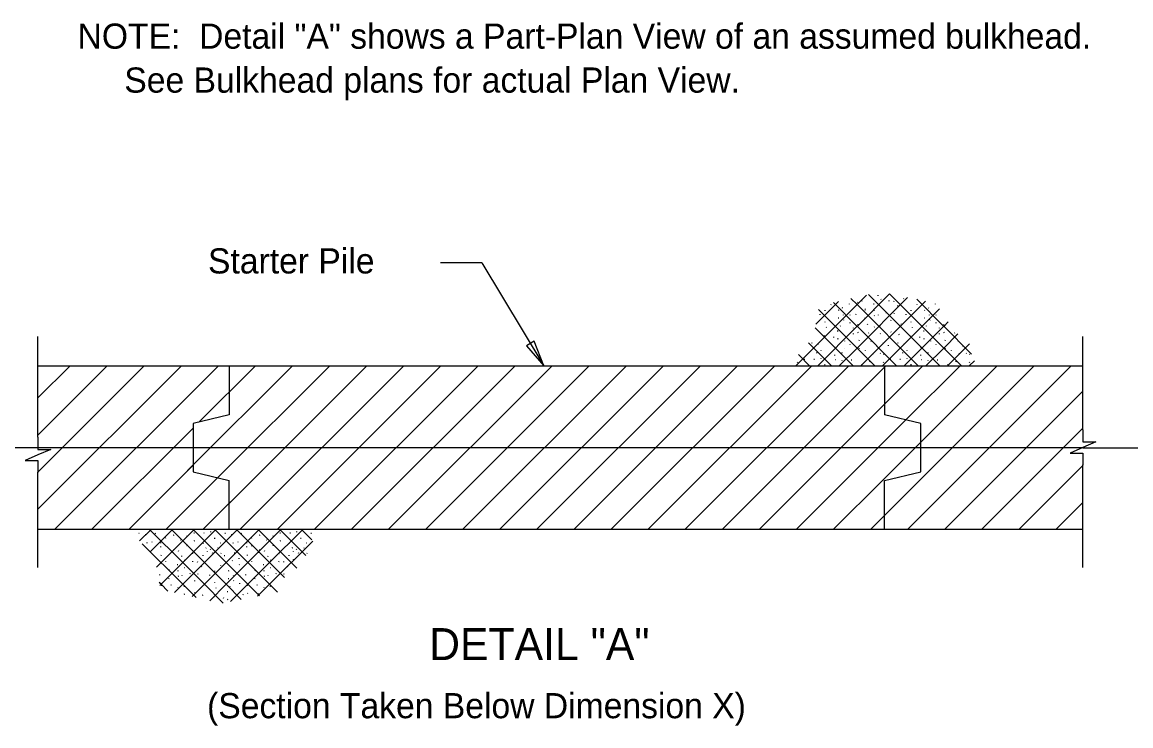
# Model space of a CAD drawing. Extents: x 0.4 to 30.4, y 0.1 to 19.4.
# Drawn here: x 4.37 to 11.03, y 0.94 to 5.17 of the extents above; entities that cross this region are included whole.
import ezdxf

# ---------------------------------------------------------------- set-up
doc = ezdxf.new("R2010")
doc.units = 0
for name, color, linetype in [('Dimension', 7, 'Continuous'), ('Miscellaneous', 7, 'Continuous'), ('SheetPileConc', 7, 'Continuous'), ('TextStructures', 7, 'Continuous')]:
    doc.layers.add(name, color=color, linetype=linetype)

msp = doc.modelspace()

# ---------------------------------------------------------------- linework, layer by layer
at = {"layer": 'Dimension'}
for p, q in [((7.1326, 3.7252), (6.8827, 3.7252)), ((7.1326, 3.7252), (7.5037, 3.1066)), ((4.4653, 2.6773), (4.4653, 3.2816)), ((10.7426, 2.7215), (10.7426, 3.2816)), ((4.4653, 1.8953), (4.4653, 2.4666)), ((10.7426, 1.8953), (10.7426, 2.5109))]:
    msp.add_line(p, q, dxfattribs=at)
msp.add_lwpolyline([(7.5037, 3.1066), (7.4461, 3.2542), (7.4007, 3.2269)], close=True, dxfattribs=at)
for points in [[(4.4653, 2.677), (4.4653, 2.6045), (4.5428, 2.6045), (4.4653, 2.5708), (4.3878, 2.537), (4.4653, 2.537), (4.4653, 2.4645)], [(10.7426, 2.7213), (10.7426, 2.6488), (10.8201, 2.6488), (10.7426, 2.615), (10.6651, 2.5813), (10.7426, 2.5813), (10.7426, 2.5088)]]:
    msp.add_lwpolyline(points, dxfattribs=at)
at = {"layer": 'Miscellaneous'}
for p, q in [((9.3854, 3.3431), (9.5807, 3.5385)), ((9.3854, 3.4734), (9.4431, 3.5311)), ((9.8835, 3.1055), (9.4551, 3.5338)), ((9.5121, 3.5267), (9.5129, 3.5298)), ((9.9062, 3.2129), (9.5806, 3.5385)), ((9.0191, 3.1071), (9.3854, 3.4734)), ((9.1373, 3.3555), (9.2742, 3.4924)), ((9.229, 3.4714), (9.2297, 3.4743)), ((9.3854, 3.3431), (9.2432, 3.4853)), ((9.34, 3.4756), (9.3407, 3.4786)), ((9.3854, 3.4734), (9.3492, 3.5096)), ((9.3854, 3.2129), (9.6891, 3.5167)), ((9.753, 3.1057), (9.3854, 3.4734)), ((9.3888, 3.4853), (9.3904, 3.4891)), ((9.409, 3.1063), (9.7974, 3.4948)), ((9.4159, 3.4937), (9.4166, 3.4966)), ((9.4881, 3.4763), (9.4842, 3.4756)), ((9.5302, 3.5049), (9.5279, 3.5057)), ((9.5775, 3.4944), (9.579, 3.4974)), ((9.607, 3.4927), (9.6078, 3.4958)), ((9.6308, 3.4645), (9.6315, 3.4674)), ((9.6658, 3.5079), (9.6651, 3.5094)), ((9.9062, 3.3431), (9.7438, 3.5056)), ((9.7459, 3.4714), (9.7466, 3.4743)), ((9.8569, 3.4756), (9.8576, 3.4786)), ((9.3854, 3.2129), (9.1535, 3.4448)), ((9.1632, 3.4124), (9.1639, 3.4154)), ((9.1933, 3.4365), (9.194, 3.4395)), ((9.2768, 3.4395), (9.273, 3.4387)), ((9.2993, 3.4523), (9.2971, 3.4546)), ((9.3038, 3.4102), (9.3046, 3.4132)), ((9.3437, 3.4102), (9.3444, 3.4132)), ((9.379, 3.4151), (9.3797, 3.418)), ((9.4346, 3.4402), (9.4362, 3.4433)), ((9.4362, 3.4455), (9.4369, 3.4486)), ((9.4911, 3.4079), (9.4881, 3.4072)), ((9.4891, 3.4385), (9.4899, 3.4415)), ((9.5136, 3.4094), (9.5143, 3.4124)), ((9.5302, 3.4575), (9.5279, 3.4583)), ((9.539, 3.1061), (9.8813, 3.4485)), ((9.5625, 3.423), (9.5633, 3.426)), ((9.6087, 3.4208), (9.6102, 3.4238)), ((9.6801, 3.4124), (9.6808, 3.4154)), ((9.7102, 3.4365), (9.7109, 3.4395)), ((9.7936, 3.4395), (9.7899, 3.4387)), ((9.8162, 3.4523), (9.814, 3.4546)), ((9.8207, 3.4102), (9.8214, 3.4132)), ((9.8606, 3.4102), (9.8613, 3.4132)), ((9.3617, 3.1064), (9.1335, 3.3346)), ((9.1491, 3.1068), (9.3854, 3.3432)), ((9.1933, 3.3673), (9.194, 3.3703)), ((9.2008, 3.3353), (9.2016, 3.3383)), ((9.2768, 3.3922), (9.273, 3.3914)), ((9.285, 3.3433), (9.2858, 3.3462)), ((9.3063, 3.3799), (9.3071, 3.3829)), ((9.3437, 3.3628), (9.3444, 3.3658)), ((9.3639, 3.332), (9.3647, 3.335)), ((9.6226, 3.1059), (9.3854, 3.3432)), ((9.3918, 3.3531), (9.3888, 3.3523)), ((9.4346, 3.3929), (9.4362, 3.3959)), ((9.4497, 3.3531), (9.4475, 3.3553)), ((9.4888, 3.3372), (9.4904, 3.3402)), ((9.5271, 3.347), (9.5242, 3.3455)), ((9.5893, 3.3786), (9.5907, 3.3816)), ((9.65, 3.3553), (9.6485, 3.3575)), ((9.6689, 3.1059), (9.9062, 3.3432)), ((9.7102, 3.3673), (9.7109, 3.3703)), ((9.7177, 3.3353), (9.7185, 3.3383)), ((9.7936, 3.3922), (9.7899, 3.3914)), ((9.8019, 3.3433), (9.8027, 3.3462)), ((9.8232, 3.3799), (9.824, 3.3829)), ((9.8606, 3.3628), (9.8613, 3.3658)), ((9.8808, 3.332), (9.8816, 3.335)), ((9.9087, 3.3531), (9.9057, 3.3523)), ((9.9062, 3.3431), (9.9328, 3.3697)), ((10.0725, 3.1768), (9.9062, 3.3432)), ((9.1903, 3.2846), (9.191, 3.2876)), ((9.246, 3.2763), (9.2467, 3.2794)), ((9.2715, 3.3146), (9.267, 3.3139)), ((9.2715, 3.2673), (9.267, 3.2665)), ((9.3639, 3.2966), (9.3647, 3.2996)), ((9.3918, 3.3057), (9.3888, 3.3049)), ((9.4549, 3.3012), (9.4557, 3.3042)), ((9.5271, 3.2996), (9.5242, 3.2982)), ((9.5908, 3.3079), (9.5894, 3.3102)), ((9.638, 3.2937), (9.6342, 3.2929)), ((9.7072, 3.2846), (9.7079, 3.2876)), ((9.7629, 3.2763), (9.7636, 3.2794)), ((9.7884, 3.3146), (9.7839, 3.3139)), ((9.7884, 3.2673), (9.7839, 3.2665)), ((9.8808, 3.2966), (9.8816, 3.2996)), ((9.9087, 3.3057), (9.9057, 3.3049)), ((9.9062, 3.2129), (9.9916, 3.2983)), ((9.9718, 3.3012), (9.9726, 3.3042)), ((9.2312, 3.1067), (9.0943, 3.2436)), ((9.1143, 3.2427), (9.115, 3.2457)), ((9.1505, 3.235), (9.1512, 3.238)), ((9.1693, 3.1974), (9.17, 3.2004)), ((9.2512, 3.2161), (9.2527, 3.2192)), ((9.279, 3.1066), (9.3854, 3.2129)), ((9.3128, 3.2545), (9.3121, 3.256)), ((9.3128, 3.2072), (9.3121, 3.2087)), ((9.3437, 3.2312), (9.3444, 3.2342)), ((9.4921, 3.1062), (9.3854, 3.2129)), ((9.3986, 3.2583), (9.3993, 3.262)), ((9.3986, 3.2109), (9.3993, 3.2146)), ((9.4362, 3.1958), (9.4369, 3.1989)), ((9.4708, 3.2516), (9.4693, 3.2523)), ((9.5053, 3.2244), (9.5023, 3.223)), ((9.5369, 3.2432), (9.5362, 3.2447)), ((9.5738, 3.2267), (9.5745, 3.2297)), ((9.6311, 3.2427), (9.6319, 3.2457)), ((9.6673, 3.235), (9.6681, 3.238)), ((9.6862, 3.1974), (9.6869, 3.2004)), ((9.7681, 3.2161), (9.7696, 3.2192)), ((9.7989, 3.1056), (9.9062, 3.2129)), ((9.8297, 3.2545), (9.829, 3.256)), ((9.8297, 3.2072), (9.829, 3.2087)), ((9.8606, 3.2312), (9.8613, 3.2342)), ((10.0139, 3.1052), (9.9062, 3.2129)), ((9.9155, 3.2583), (9.9162, 3.262)), ((9.9155, 3.2109), (9.9162, 3.2146)), ((9.9289, 3.1054), (10.061, 3.2375)), ((9.9531, 3.1958), (9.9538, 3.1989)), ((9.9877, 3.2516), (9.9862, 3.2523)), ((10.0222, 3.2244), (10.0192, 3.223)), ((9.1008, 3.1069), (9.0329, 3.1748)), ((9.071, 3.144), (9.0672, 3.1432)), ((9.1301, 3.144), (9.1264, 3.1432)), ((9.1436, 3.1824), (9.1444, 3.1853)), ((9.1693, 3.1492), (9.17, 3.1523)), ((9.2512, 3.1688), (9.2527, 3.1718)), ((9.2564, 3.1417), (9.2534, 3.141)), ((9.2956, 3.1824), (9.2956, 3.1853)), ((9.2956, 3.135), (9.2956, 3.138)), ((9.3542, 3.1402), (9.3505, 3.1395)), ((9.4625, 3.1305), (9.464, 3.1335)), ((9.464, 3.129), (9.4647, 3.132)), ((9.4835, 3.1786), (9.4798, 3.1779)), ((9.5256, 3.1801), (9.5242, 3.1824)), ((9.5444, 3.1733), (9.546, 3.1763)), ((9.5879, 3.144), (9.5841, 3.1432)), ((9.647, 3.144), (9.6433, 3.1432)), ((9.6605, 3.1824), (9.6613, 3.1853)), ((9.6862, 3.1492), (9.6869, 3.1523)), ((9.7681, 3.1688), (9.7696, 3.1718)), ((9.7733, 3.1417), (9.7703, 3.141)), ((9.8125, 3.1824), (9.8125, 3.1853)), ((9.8125, 3.135), (9.8125, 3.138)), ((9.8711, 3.1402), (9.8673, 3.1395)), ((9.9794, 3.1305), (9.9809, 3.1335)), ((9.9809, 3.129), (9.9816, 3.132)), ((10.0004, 3.1786), (9.9967, 3.1779)), ((10.0425, 3.1801), (10.041, 3.1824)), ((10.0588, 3.1051), (10.0902, 3.1365)), ((10.0613, 3.1733), (10.0629, 3.1763)), ((4.4653, 2.9132), (4.6587, 3.1066)), ((4.4653, 2.6905), (4.8814, 3.1066)), ((4.4653, 2.4678), (5.1042, 3.1066)), ((4.4653, 2.245), (5.3269, 3.1066)), ((4.5653, 2.1223), (5.5496, 3.1066)), ((5.3648, 2.4764), (5.9951, 3.1066)), ((5.4348, 2.7691), (5.7724, 3.1066)), ((5.545, 2.4338), (6.2178, 3.1066)), ((5.6137, 2.2797), (6.4406, 3.1066)), ((5.679, 2.1223), (6.6633, 3.1066)), ((5.9017, 2.1223), (6.8861, 3.1066)), ((6.1244, 2.1223), (7.1088, 3.1066)), ((6.3471, 2.1223), (7.3315, 3.1066)), ((6.5699, 2.1223), (7.5543, 3.1066)), ((6.7926, 2.1223), (7.777, 3.1066)), ((7.0154, 2.1223), (7.9998, 3.1066)), ((7.2381, 2.1223), (8.2225, 3.1066)), ((7.4608, 2.1223), (8.4452, 3.1066)), ((7.6836, 2.1223), (8.6679, 3.1066)), ((7.9063, 2.1223), (8.8907, 3.1066)), ((8.1291, 2.1223), (9.1134, 3.1066)), ((8.3518, 2.1223), (9.3362, 3.1066)), ((8.5745, 2.1223), (9.5589, 3.1066)), ((9.0275, 3.1259), (9.0291, 3.129)), ((9.1948, 3.1117), (9.1903, 3.1117)), ((9.4136, 3.1124), (9.4159, 3.1154)), ((9.4655, 2.1223), (10.4499, 3.1066)), ((9.4663, 2.7912), (9.7816, 3.1066)), ((9.534, 2.4135), (10.2271, 3.1066)), ((9.5444, 3.1259), (9.546, 3.129)), ((9.6789, 2.7811), (10.0044, 3.1066)), ((9.6882, 2.1223), (10.6726, 3.1066)), ((9.7117, 3.1117), (9.7072, 3.1117)), ((9.9305, 3.1124), (9.9328, 3.1154)), ((10.0613, 3.1259), (10.0629, 3.129)), ((9.911, 2.1223), (10.7426, 2.9539)), ((8.7973, 2.1223), (9.5512, 2.8761)), ((4.788, 2.1223), (5.3971, 2.7314)), ((9.02, 2.1223), (9.679, 2.7811)), ((10.1337, 2.1223), (10.7426, 2.7312)), ((4.4653, 2.6144), (4.0715, 2.6144)), ((10.7426, 2.6144), (4.4653, 2.6144)), ((10.7426, 2.6144), (11.1364, 2.6144)), ((5.0107, 2.1223), (5.3971, 2.5086)), ((10.3564, 2.1223), (10.7426, 2.5084)), ((5.2335, 2.1223), (5.545, 2.4338)), ((5.4562, 2.1223), (5.7942, 2.4603)), ((9.2427, 2.1223), (9.5405, 2.4201)), ((10.5791, 2.1223), (10.7426, 2.2858)), ((5.0742, 2.0996), (5.0712, 2.0989)), ((5.0761, 2.0555), (5.1426, 2.122)), ((5.1133, 2.0928), (5.1133, 2.0958)), ((5.1375, 1.9866), (5.2731, 2.1222)), ((5.3355, 1.9242), (5.1378, 2.122)), ((5.1719, 2.0981), (5.1682, 2.0973)), ((5.2313, 2.0703), (5.2336, 2.0732)), ((5.3355, 2.0544), (5.2678, 2.1222)), ((5.2802, 2.0883), (5.2817, 2.0913)), ((5.2817, 2.0868), (5.2824, 2.0898)), ((5.3355, 1.794), (5.6644, 2.1229)), ((5.3355, 1.9242), (5.534, 2.1227)), ((5.3355, 2.0544), (5.4035, 2.1225)), ((5.3621, 2.0838), (5.3637, 2.0868)), ((5.7262, 1.794), (5.3978, 2.1224)), ((5.4056, 2.1019), (5.4018, 2.1011)), ((5.4648, 2.1019), (5.461, 2.1011)), ((5.4657, 1.794), (5.7948, 2.1232)), ((5.5039, 2.1071), (5.5046, 2.1102)), ((5.5294, 2.0695), (5.5249, 2.0695)), ((5.8561, 1.7943), (5.5277, 2.1227)), ((5.5911, 2.0996), (5.5881, 2.0989)), ((5.6302, 2.0928), (5.6302, 2.0958)), ((5.8564, 1.9242), (5.6577, 2.1229)), ((5.6888, 2.0981), (5.6851, 2.0973)), ((5.7482, 2.0703), (5.7505, 2.0732)), ((5.8564, 2.0544), (5.7877, 2.1232)), ((5.7971, 2.0883), (5.7986, 2.0913)), ((5.7986, 2.0868), (5.7993, 2.0898)), ((5.8564, 1.9242), (6.0558, 2.1237)), ((5.8564, 2.0544), (5.9253, 2.1234)), ((5.879, 2.0838), (5.8806, 2.0868)), ((6.0737, 1.9674), (5.9177, 2.1234)), ((5.9225, 2.1019), (5.9187, 2.1011)), ((5.9816, 2.1019), (5.9779, 2.1011)), ((6.0208, 2.1071), (6.0215, 2.1102)), ((6.0463, 2.0695), (6.0418, 2.0695)), ((6.1101, 2.0612), (6.0476, 2.1236)), ((6.108, 2.0996), (6.105, 2.0989)), ((6.1786, 2.1229), (6.1776, 2.1239)), ((5.3353, 1.7943), (5.0922, 2.0373)), ((5.1215, 2.0417), (5.1223, 2.0447)), ((5.1509, 2.0462), (5.1501, 2.0477)), ((5.1509, 1.9989), (5.1501, 2.0004)), ((5.1776, 1.8965), (5.3355, 2.0545)), ((5.2035, 2.0417), (5.2042, 2.0447)), ((5.2035, 2.0176), (5.2042, 2.0206)), ((5.2313, 2.0229), (5.2336, 2.0259)), ((5.2817, 1.9996), (5.2824, 2.0026)), ((5.3231, 2.0583), (5.3216, 2.0605)), ((5.596, 1.794), (5.3355, 2.0545)), ((5.3614, 2.0259), (5.3607, 2.0274)), ((5.3645, 2.0282), (5.3614, 2.0282)), ((5.4056, 2.0545), (5.4018, 2.0537)), ((5.4591, 2.0387), (5.4599, 2.0417)), ((5.4768, 2.0124), (5.473, 2.0116)), ((5.5023, 2.0033), (5.5031, 2.0064)), ((5.5467, 2.0102), (5.5474, 2.0131)), ((5.5633, 2.0402), (5.5618, 2.0409)), ((5.596, 1.794), (5.8564, 2.0545)), ((5.6384, 2.0417), (5.6392, 2.0447)), ((5.6677, 2.0462), (5.667, 2.0477)), ((5.6677, 1.9989), (5.667, 2.0004)), ((5.7204, 2.0417), (5.7211, 2.0447)), ((5.7204, 2.0176), (5.7211, 2.0206)), ((5.7482, 2.0229), (5.7505, 2.0259)), ((5.7986, 1.9996), (5.7993, 2.0026)), ((5.8399, 2.0583), (5.8385, 2.0605)), ((6.0196, 1.8912), (5.8564, 2.0545)), ((5.8564, 1.794), (6.1159, 2.0535)), ((5.8783, 2.0259), (5.8776, 2.0274)), ((5.8814, 2.0282), (5.8783, 2.0282)), ((5.9225, 2.0545), (5.9187, 2.0537)), ((5.976, 2.0387), (5.9768, 2.0417)), ((5.9937, 2.0124), (5.9899, 2.0116)), ((6.0192, 2.0033), (6.02, 2.0064)), ((6.0636, 2.0102), (6.0643, 2.0131)), ((6.0802, 2.0402), (6.0787, 2.0409)), ((5.2065, 1.9673), (5.2081, 1.971)), ((5.278, 1.9838), (5.2794, 1.9869)), ((5.3103, 1.9935), (5.3118, 1.9973)), ((5.3298, 1.9612), (5.3306, 1.9643)), ((5.3479, 1.9395), (5.3456, 1.9402)), ((5.3953, 1.9763), (5.3968, 1.9793)), ((5.3953, 1.9289), (5.3968, 1.9319)), ((5.4576, 1.9658), (5.4583, 1.9688)), ((5.4836, 1.9425), (5.4828, 1.944)), ((5.4836, 1.9898), (5.4831, 1.9906)), ((5.5136, 1.9815), (5.5151, 1.9853)), ((5.564, 1.9785), (5.5655, 1.9815)), ((5.5881, 1.9658), (5.5844, 1.965)), ((5.634, 1.9342), (5.6317, 1.9365)), ((5.6474, 1.9815), (5.6437, 1.98)), ((5.6738, 1.947), (5.6746, 1.95)), ((5.7234, 1.9673), (5.725, 1.971)), ((5.7949, 1.9838), (5.7963, 1.9869)), ((5.8272, 1.9935), (5.8287, 1.9973)), ((5.8467, 1.9612), (5.8475, 1.9643)), ((5.8648, 1.9395), (5.8625, 1.9402)), ((5.9122, 1.9763), (5.9136, 1.9793)), ((5.9122, 1.9289), (5.9136, 1.9319)), ((5.9745, 1.9658), (5.9752, 1.9688)), ((6.0005, 1.9425), (5.9997, 1.944)), ((6.0005, 1.9898), (6, 1.9906)), ((6.0305, 1.9815), (6.032, 1.9853)), ((6.0809, 1.9785), (6.0824, 1.9815)), ((5.2053, 1.794), (5.3355, 1.9242)), ((5.2065, 1.9199), (5.2081, 1.9237)), ((5.2336, 1.9282), (5.2343, 1.9311)), ((5.2524, 1.8748), (5.2539, 1.8778)), ((5.2539, 1.88), (5.2546, 1.8831)), ((5.3058, 1.9108), (5.302, 1.9101)), ((5.3068, 1.8731), (5.3076, 1.876)), ((5.4657, 1.794), (5.3355, 1.9242)), ((5.3479, 1.8921), (5.3456, 1.8929)), ((5.4247, 1.9272), (5.4255, 1.9303)), ((5.4485, 1.899), (5.4493, 1.902)), ((5.5279, 1.871), (5.5286, 1.874)), ((5.5636, 1.9059), (5.5644, 1.9089)), ((5.6114, 1.874), (5.6076, 1.8733)), ((5.634, 1.8869), (5.6317, 1.8891)), ((5.6746, 1.9101), (5.6753, 1.9132)), ((5.7234, 1.9199), (5.725, 1.9237)), ((5.7262, 1.794), (5.8564, 1.9242)), ((5.7505, 1.9282), (5.7512, 1.9311)), ((5.7692, 1.8748), (5.7708, 1.8778)), ((5.7708, 1.88), (5.7715, 1.8831)), ((5.8227, 1.9108), (5.8189, 1.9101)), ((5.8237, 1.8731), (5.8245, 1.876)), ((5.9455, 1.8351), (5.8564, 1.9242)), ((5.8648, 1.8921), (5.8625, 1.8929)), ((5.9416, 1.9272), (5.9424, 1.9303)), ((5.9654, 1.899), (5.9662, 1.902)), ((5.2053, 1.794), (5.1941, 1.8052)), ((5.1967, 1.8496), (5.1975, 1.8526)), ((5.2524, 1.8274), (5.2539, 1.8304)), ((5.3088, 1.8425), (5.3058, 1.8417)), ((5.3313, 1.844), (5.332, 1.847)), ((5.3802, 1.8575), (5.381, 1.8605)), ((5.407, 1.8132), (5.4084, 1.8162)), ((5.4264, 1.8554), (5.4279, 1.8584)), ((5.4978, 1.847), (5.4985, 1.85)), ((5.5279, 1.8018), (5.5286, 1.8048)), ((5.6114, 1.8267), (5.6076, 1.8259)), ((5.6384, 1.8447), (5.6392, 1.8477)), ((5.6409, 1.8145), (5.6417, 1.8174)), ((5.6783, 1.8447), (5.679, 1.8477)), ((5.6783, 1.7974), (5.679, 1.8003)), ((5.7136, 1.8496), (5.7144, 1.8526)), ((5.7692, 1.8274), (5.7708, 1.8304)), ((5.8257, 1.8425), (5.8227, 1.8417)), ((5.8482, 1.844), (5.8489, 1.847)), ((5.8971, 1.8575), (5.8979, 1.8605)), ((5.9433, 1.8554), (5.9448, 1.8584)), ((5.1975, 1.7862), (5.2053, 1.794)), ((5.2463, 1.7531), (5.2053, 1.794)), ((5.2095, 1.7876), (5.2065, 1.7868)), ((5.2675, 1.7876), (5.2652, 1.7898)), ((5.2856, 1.7441), (5.3355, 1.794)), ((5.3065, 1.7718), (5.3081, 1.7748)), ((5.4152, 1.7144), (5.3355, 1.794)), ((5.3449, 1.7815), (5.3419, 1.78)), ((5.3449, 1.7341), (5.3419, 1.7327)), ((5.3915, 1.7198), (5.4657, 1.794)), ((5.4086, 1.7425), (5.4071, 1.7447)), ((5.5788, 1.681), (5.4657, 1.794)), ((5.4677, 1.7898), (5.4663, 1.7921)), ((5.4975, 1.6955), (5.596, 1.794)), ((5.5355, 1.7699), (5.5362, 1.7728)), ((5.6871, 1.7029), (5.596, 1.794)), ((5.6061, 1.7492), (5.6016, 1.7485)), ((5.6196, 1.7778), (5.6204, 1.7808)), ((5.6218, 1.6897), (5.7262, 1.794)), ((5.6985, 1.7666), (5.6993, 1.7695)), ((5.6985, 1.7311), (5.6993, 1.7341)), ((5.7264, 1.7876), (5.7234, 1.7868)), ((5.7264, 1.7402), (5.7234, 1.7394)), ((5.7955, 1.7247), (5.7262, 1.794)), ((5.7844, 1.7876), (5.7821, 1.7898)), ((5.785, 1.7226), (5.8564, 1.794)), ((5.7896, 1.7357), (5.7903, 1.7387)), ((5.8234, 1.7718), (5.825, 1.7748)), ((5.9038, 1.7466), (5.8564, 1.794)), ((5.8618, 1.7815), (5.8588, 1.78)), ((5.4557, 1.7282), (5.4519, 1.7274)), ((5.5249, 1.7191), (5.5256, 1.7222)), ((5.5806, 1.7108), (5.5813, 1.7139)), ((5.6061, 1.7018), (5.6016, 1.7011))]:
    msp.add_line(p, q, dxfattribs=at)
at = {"layer": 'SheetPileConc'}
for p, q in [((4.4653, 3.1066), (9.5512, 3.1066)), ((5.6137, 3.1066), (5.6137, 2.8113)), ((9.5512, 3.1066), (9.5512, 2.8113)), ((9.5512, 3.1066), (10.7426, 3.1066)), ((5.6137, 2.8113), (5.3971, 2.7601)), ((9.7677, 2.7601), (9.5512, 2.8113)), ((5.3971, 2.7601), (5.3971, 2.4687)), ((9.7677, 2.4687), (9.7677, 2.7601)), ((5.3971, 2.4687), (5.6137, 2.4176)), ((9.5512, 2.4176), (9.7677, 2.4687)), ((5.6137, 2.1223), (5.6137, 2.4176)), ((9.5512, 2.1223), (9.5512, 2.4176)), ((9.5512, 2.1223), (4.4653, 2.1223)), ((10.7426, 2.1223), (9.5512, 2.1223))]:
    msp.add_line(p, q, dxfattribs=at)

# ---------------------------------------------------------------- texts
at = {"layer": 'Dimension'}
for s, p in [('NOTE:  Detail "A" shows a Part-Plan View of an assumed bulkhead. ', (4.7034, 5.0105)), ('     See Bulkhead plans for actual Plan View.            ', (4.7034, 4.7465))]:
    msp.add_text(s, height=0.1512, dxfattribs=at).set_placement(p)
at = {"layer": 'TextStructures'}
for s, height, p in [('Starter Pile', 0.1512, (5.487, 3.6605)), ('DETAIL "A"', 0.192, (6.8152, 1.3388)), ('(Section Taken Below Dimension X)', 0.1512, (5.4814, 0.9896))]:
    msp.add_text(s, height=height, dxfattribs=at).set_placement(p)

doc.saveas('drawing.dxf')
